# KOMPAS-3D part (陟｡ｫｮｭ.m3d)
File: created 29.01.2016 13:47:21, last saved 25.07.2016 11:16:00.
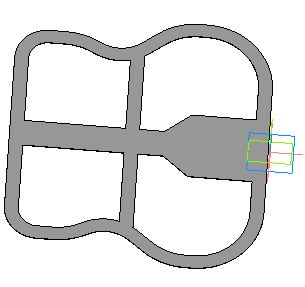
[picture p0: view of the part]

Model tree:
1. Эскиз:1
2. Операция выдавливания:1
     Толщина стенки 2 = 18; Расстояние 1 = 0.6
3. Эскиз:2
4. Вырезать элемент выдавливания:1
     Толщина стенки 2 = 2; Расстояние 1 = 30
5. Эскиз:3
6. Операция выдавливания:2
     Расстояние 1 = 0.6
7. Эскиз:4
8. Операция выдавливания:3
     Расстояние 1 = 0.6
